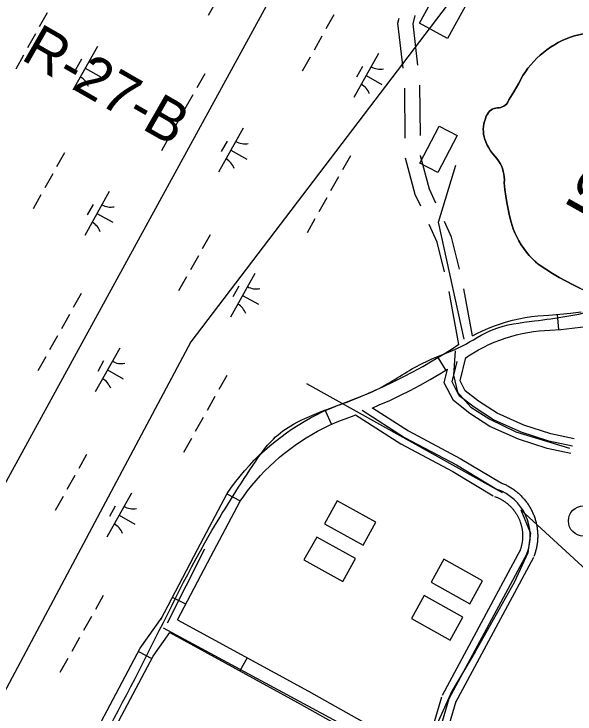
# Model space of a CAD drawing. Extents: x 3913936 to 3933962, y 195330 to 217741.
# Drawn here: x 3928535 to 3929093, y 208398 to 209094 of the extents above; entities that cross this region are included whole.
import ezdxf

# ---------------------------------------------------------------- set-up
doc = ezdxf.new("R2010")
doc.units = 0
for name, color, linetype in [('V-BLDG-OTLN', 7, 'Continuous'), ('V-RIVR-IDEN', 7, 'Continuous'), ('V-RIVR-RANG-IDEN', 7, 'Continuous'), ('V-ROAD-CNTR', 7, 'Continuous'), ('V-TOPO-SHOR', 7, 'Continuous'), ('V-TOPO-TOWR', 7, 'Continuous'), ('V-UTIL-LINE', 7, 'Continuous'), ('V-WETL-SWMP', 7, 'Continuous')]:
    doc.layers.add(name, color=color, linetype=linetype)

msp = doc.modelspace()

# ---------------------------------------------------------------- linework, layer by layer
at = {"layer": 'V-BLDG-OTLN'}
for points in [[(3928938.51, 209085.2), (3928961.65, 209127.6), (3928989.66, 209112.32), (3928966.52, 209069.91)], [(3928938.98, 208945.79), (3928958.17, 208982.69), (3928975.95, 208973.44), (3928956.76, 208936.54)], [(3928895.17, 208588.41), (3928856.57, 208609.83), (3928843.88, 208586.96), (3928882.47, 208565.54)], [(3928874.79, 208552.28), (3928836.2, 208573.7), (3928823.5, 208550.83), (3928862.1, 208529.4)], [(3929001.34, 208530.17), (3928962.74, 208551.59), (3928950.05, 208528.71), (3928988.64, 208507.29)], [(3928981.71, 208493.91), (3928943.12, 208515.33), (3928930.42, 208492.46), (3928969.02, 208471.04)]]:
    msp.add_lwpolyline(points, close=True, dxfattribs=at)
at = {"layer": 'V-ROAD-CNTR'}
for p, q in [((3928924.39, 208970.57), (3928923.87, 209020.56)), ((3928939.36, 208973.33), (3928938.84, 209023.32)), ((3928977.74, 208765.41), (3928968.01, 208818.05)), ((3928991.42, 208773.91), (3928982.76, 208820.78)), ((3929075.64, 208795.14), (3929076.77, 208780.18)), ((3928956.82, 208752.31), (3928964.58, 208739.48)), ((3928844.76, 208699.53), (3928850.89, 208685.84)), ((3928746.88, 208616.62), (3928760.12, 208609.58)), ((3928692.2, 208513.99), (3928705.59, 208507.24)), ((3928658.87, 208459.89), (3928672.12, 208452.87)), ((3928766.83, 208453.57), (3928759.64, 208440.41))]:
    msp.add_line(p, q, dxfattribs=at)
for points in [[(3928922.25, 209040.47), (3928917.11, 209085.13), (3928918.16, 209090.07)], [(3928937.03, 209043.22), (3928932.29, 209084.41), (3928934.06, 209092.76)], [(3928939.72, 208903.03), (3928934.34, 208914.7), (3928924.73, 208950.59)], [(3928954.91, 208905.91), (3928948.5, 208919.82), (3928939.57, 208953.18), (3928939.57, 208953.33)], [(3928983.1, 208770.49), (3928957.57, 208887.13), (3928974.71, 208943.85)], [(3928978.21, 208840.25), (3928970.48, 208872.11), (3928963.28, 208887.74)], [(3928963.44, 208837.52), (3928956.25, 208867.16), (3928948.09, 208884.87)], [(3928991.18, 208773.77), (3928995.66, 208776.14), (3929001.37, 208778.89), (3929007.18, 208781.44), (3929013.07, 208783.78), (3929019.05, 208785.89), (3929025.11, 208787.79), (3929031.22, 208789.46), (3929037.39, 208790.91), (3929043.61, 208792.14), (3929049.88, 208793.13), (3929056.29, 208793.91), (3929067.36, 208794.51), (3929078.08, 208795.33), (3929088.78, 208796.38), (3929099.46, 208797.66)], [(3928984.49, 208752.16), (3928987.35, 208754.05), (3928992.29, 208757.15), (3928997.31, 208760.04), (3929002.43, 208762.75), (3929007.65, 208765.27), (3929012.95, 208767.6), (3929018.34, 208769.73), (3929023.8, 208771.66), (3929029.33, 208773.39), (3929034.92, 208774.92), (3929040.56, 208776.25), (3929046.24, 208777.37), (3929051.96, 208778.28), (3929057.6, 208778.96), (3929068.33, 208779.54), (3929079.38, 208780.38), (3929090.41, 208781.46), (3929101.41, 208782.79)], [(3928717.56, 208561.42), (3928747.16, 208617.15), (3928751.38, 208623.2), (3928755.57, 208628.84), (3928759.93, 208634.35), (3928764.46, 208639.72), (3928769.15, 208644.96), (3928773.98, 208650.05), (3928778.97, 208655), (3928784.11, 208659.79), (3928789.39, 208664.44), (3928794.81, 208668.91), (3928800.35, 208673.23), (3928806.03, 208677.37), (3928811.83, 208681.34), (3928817.74, 208685.14), (3928823.76, 208688.76), (3928829.89, 208692.19), (3928836.12, 208695.44), (3928842.45, 208698.5), (3928848.86, 208701.37), (3928855.36, 208704.04), (3928861.83, 208706.48), (3928865.36, 208707.82), (3928872.17, 208710.4), (3928882.38, 208714.51), (3928892.5, 208718.83), (3928902.53, 208723.34), (3928912.47, 208728.06), (3928922.31, 208732.98), (3928932.05, 208738.1), (3928941.68, 208743.41), (3928951.2, 208748.91), (3928960.62, 208754.61), (3928969.91, 208760.49), (3928977.73, 208765.67)], [(3928973.98, 208759.07), (3928972.29, 208734.65), (3928976.41, 208717.78), (3928989.5, 208702.87), (3929008.65, 208691.07), (3929034.39, 208678.42), (3929087.88, 208662.16)], [(3929090.84, 208664.14), (3929067.42, 208669.11), (3929039.72, 208678.13), (3929012.18, 208690.33), (3928992.96, 208702.78), (3928978.17, 208714.36), (3928971.17, 208728.13), (3928975.99, 208748.36)], [(3929092.4, 208671.47), (3929069.37, 208676.36), (3929042.41, 208685.14), (3929015.76, 208696.95), (3928997.32, 208708.89), (3928984.1, 208719.24), (3928979.1, 208729.08), (3928984.66, 208752.42)], [(3928891.25, 208701.99), (3928898.52, 208705.09), (3928908.83, 208709.73), (3928919.04, 208714.58), (3928929.15, 208719.63), (3928939.16, 208724.89), (3928949.06, 208730.35), (3928958.84, 208736), (3928966.56, 208740.68)], [(3929089.28, 208656.8), (3929065.48, 208661.85), (3929037.04, 208671.11), (3929008.6, 208683.72), (3928988.6, 208696.66), (3928972.24, 208709.48), (3928963.23, 208727.19), (3928966.47, 208740.78)], [(3929021.06, 208617.58), (3928826.4, 208726.25)], [(3928881.55, 208699.87), (3928923.72, 208672.88), (3928975.47, 208645.43), (3929015.85, 208621.09)], [(3928891.79, 208702.22), (3928927.51, 208679.36), (3928979.16, 208651.96), (3929019.73, 208627.51)], [(3928730.81, 208554.39), (3928759.98, 208609.31), (3928763.55, 208614.42), (3928767.47, 208619.7), (3928771.56, 208624.86), (3928775.79, 208629.89), (3928780.17, 208634.79), (3928784.7, 208639.56), (3928789.38, 208644.19), (3928794.18, 208648.68), (3928799.12, 208653.02), (3928804.19, 208657.21), (3928809.38, 208661.25), (3928814.69, 208665.12), (3928820.12, 208668.84), (3928825.65, 208672.39), (3928831.29, 208675.78), (3928837.03, 208679), (3928842.86, 208682.04), (3928848.78, 208684.9), (3928854.78, 208687.59), (3928860.86, 208690.09), (3928867.13, 208692.45), (3928870.68, 208693.8), (3928875.03, 208695.45)], [(3928874.72, 208695.33), (3928919.94, 208666.4), (3928971.77, 208638.9), (3929011.98, 208614.67)], [(3929018.38, 208628.15), (3929019.27, 208627.83), (3929020.21, 208627.47), (3929021.1, 208627.11), (3929022.01, 208626.73), (3929022.94, 208626.32), (3929023.81, 208625.91), (3929024.7, 208625.49), (3929025.6, 208625.03), (3929026.47, 208624.57), (3929027.34, 208624.09), (3929028.17, 208623.61), (3929029.02, 208623.11), (3929029.89, 208622.57), (3929030.71, 208622.03), (3929031.52, 208621.49), (3929032.33, 208620.93), (3929033.14, 208620.34), (3929033.93, 208619.75), (3929034.72, 208619.14), (3929035.47, 208618.53), (3929036.23, 208617.89), (3929036.99, 208617.24), (3929037.71, 208616.59), (3929038.44, 208615.92), (3929039.16, 208615.23), (3929039.86, 208614.53), (3929040.54, 208613.83), (3929041.22, 208613.1), (3929041.89, 208612.35), (3929042.53, 208611.63), (3929043.16, 208610.88), (3929043.79, 208610.1), (3929044.41, 208609.31), (3929044.99, 208608.54), (3929045.58, 208607.74), (3929046.16, 208606.91), (3929046.7, 208606.11), (3929047.24, 208605.3), (3929047.78, 208604.44), (3929048.28, 208603.6), (3929048.78, 208602.74), (3929049.25, 208601.89), (3929049.72, 208601.02), (3929050.18, 208600.12), (3929050.61, 208599.25), (3929051.02, 208598.36), (3929051.44, 208597.44), (3929051.82, 208596.54), (3929052.19, 208595.64), (3929052.55, 208594.71), (3929052.89, 208593.78), (3929053.22, 208592.83), (3929053.52, 208591.9), (3929053.81, 208590.98), (3929054.09, 208590.01), (3929054.35, 208589.05), (3929054.58, 208588.11), (3929054.81, 208587.13), (3929055.02, 208586.15), (3929055.21, 208585.2), (3929055.38, 208584.24), (3929055.54, 208583.26), (3929055.68, 208582.26), (3929055.8, 208581.29), (3929055.91, 208580.32), (3929056, 208579.32), (3929056.07, 208578.33), (3929056.12, 208577.36), (3929056.16, 208576.36), (3929056.18, 208575.37), (3929056.18, 208574.4), (3929056.17, 208573.4), (3929056.13, 208572.42), (3929056.09, 208571.42), (3929056.02, 208570.43), (3929055.94, 208569.47), (3929055.84, 208568.49), (3929055.71, 208567.47), (3929055.58, 208566.5), (3929055.43, 208565.55), (3929055.26, 208564.57), (3929055.08, 208563.61), (3929054.87, 208562.61), (3929054.64, 208561.65), (3929054.42, 208560.72), (3929054.16, 208559.74), (3929053.88, 208558.79), (3929053.61, 208557.87), (3929053.3, 208556.91), (3929052.98, 208555.98), (3929052.65, 208555.05), (3929052.36, 208554.31)], [(3929013.32, 208614.03), (3929014.05, 208613.77), (3929014.71, 208613.52), (3929015.41, 208613.24), (3929016.08, 208612.95), (3929016.73, 208612.67), (3929017.4, 208612.35), (3929018.06, 208612.04), (3929018.69, 208611.72), (3929019.33, 208611.38), (3929019.97, 208611.02), (3929020.61, 208610.65), (3929021.24, 208610.28), (3929021.84, 208609.91), (3929022.44, 208609.52), (3929023.06, 208609.1), (3929023.65, 208608.69), (3929024.24, 208608.26), (3929024.82, 208607.83), (3929025.39, 208607.39), (3929025.97, 208606.92), (3929026.52, 208606.46), (3929027.06, 208606), (3929027.61, 208605.5), (3929028.14, 208605.01), (3929028.66, 208604.51), (3929029.18, 208603.99), (3929029.69, 208603.46), (3929030.18, 208602.94), (3929030.66, 208602.41), (3929031.15, 208601.85), (3929031.62, 208601.29), (3929032.07, 208600.74), (3929032.51, 208600.18), (3929032.97, 208599.58), (3929033.39, 208599), (3929033.8, 208598.42), (3929034.22, 208597.8), (3929034.62, 208597.18), (3929034.99, 208596.59), (3929035.37, 208595.96), (3929035.74, 208595.33), (3929036.09, 208594.69), (3929036.44, 208594.05), (3929036.76, 208593.42), (3929037.09, 208592.75), (3929037.4, 208592.09), (3929037.69, 208591.45), (3929037.97, 208590.77), (3929038.25, 208590.09), (3929038.51, 208589.42), (3929038.77, 208588.73), (3929039, 208588.06), (3929039.22, 208587.36), (3929039.45, 208586.65), (3929039.64, 208585.97), (3929039.83, 208585.28), (3929040.01, 208584.55), (3929040.18, 208583.85), (3929040.32, 208583.16), (3929040.47, 208582.44), (3929040.6, 208581.7), (3929040.71, 208581), (3929040.81, 208580.29), (3929040.9, 208579.56), (3929040.98, 208578.83), (3929041.05, 208578.11), (3929041.1, 208577.39), (3929041.14, 208576.65), (3929041.17, 208575.94), (3929041.18, 208575.22), (3929041.18, 208574.48), (3929041.17, 208573.75), (3929041.15, 208573.04), (3929041.11, 208572.32), (3929041.06, 208571.59), (3929041, 208570.84), (3929040.93, 208570.13), (3929040.84, 208569.43), (3929040.74, 208568.71), (3929040.63, 208567.97), (3929040.5, 208567.25), (3929040.37, 208566.54), (3929040.22, 208565.85), (3929040.06, 208565.14), (3929039.88, 208564.41), (3929039.7, 208563.73), (3929039.5, 208563.03), (3929039.28, 208562.32), (3929039.07, 208561.64), (3929038.83, 208560.95), (3929038.58, 208560.26), (3929038.35, 208559.68)], [(3930823.01, 206963.04), (3929039.41, 208600.73), (3929049.15, 208577.59), (3929046.49, 208558.09), (3929032.64, 208528.59), (3928993.92, 208459.57), (3928970.67, 208420.27), (3928954.36, 208384.07), (3928945.59, 208353.96), (3928950.18, 208316.41), (3928961.96, 208239.89), (3928974.02, 208141.9), (3928981.7, 208066.95), (3928978.5, 208011.84), (3928972.63, 207973.03), (3928962.24, 207947.24), (3928936.56, 207903.58), (3928904.2, 207841.96)], [(3928680.95, 208491.66), (3928717.56, 208561.42)], [(3928687.65, 208488.29), (3928724.81, 208562.06)], [(3929038.75, 208560.54), (3928961.18, 208416.11)], [(3928697.61, 208491.39), (3928730.81, 208554.39)], [(3929045.36, 208556.99), (3928967.79, 208412.57)], [(3929051.96, 208553.44), (3928974.39, 208409.02)], [(3928044.19, 207343.61), (3928094.47, 207444.55), (3928133.32, 207517.5), (3928180.5, 207605.25), (3928235.42, 207695.27), (3928288.75, 207774.86), (3928328.21, 207845.05), (3928371.81, 207914.97), (3928403.35, 207978.71), (3928448.6, 208063.04), (3928487.61, 208140.09), (3928551.26, 208257.15), (3928589.13, 208328.33), (3928660.52, 208463.01), (3928682.44, 208493.91)], [(3928697.61, 208491.39), (3928827.89, 208420.21), (3928926.42, 208364.82), (3928942.48, 208352.95)], [(3928947.64, 208339.98), (3928899.56, 208366.53), (3928683.7, 208482.82)], [(3928500.9, 208133.12), (3928564.47, 208250.04), (3928602.37, 208321.29), (3928673.32, 208455.12), (3928689.91, 208478.51), (3928820.62, 208407.09), (3928918.26, 208352.2), (3928940.13, 208336.04), (3928946.44, 208313.53), (3928967.35, 208141.02), (3928975.79, 208057.33), (3928972.53, 208007.03)], [(3928942.48, 208352.95), (3928960.59, 208414.68)], [(3928967.79, 208412.57), (3928948.91, 208348.2)], [(3928954.46, 208340.49), (3928974.98, 208410.45)]]:
    msp.add_lwpolyline(points, dxfattribs=at)
msp.add_arc((3928999.57, 208574.75), 49.12, 338.79873, 70.63267, dxfattribs=at)
msp.add_spline([(3928525.94, 208199.58), (3928663.47, 208448.7), (3928729.28, 208575.65), (3928772.51, 208644.8), (3928793.04, 208671.23), (3928813.16, 208685.99), (3928849.99, 208702.06), (3928901.39, 208723.29), (3928941.15, 208746.48), (3928980.61, 208763.64), (3929011.73, 208780.24), (3929053.09, 208788.77), (3929116.61, 208799.68), (3929152.59, 208808.41), (3929198.09, 208822), (3929228.27, 208840.26), (3929280.48, 208872.74), (3929342.15, 208906.58), (3929394.32, 208930.8), (3929439.03, 208947.65), (3929467.84, 208956.79), (3929496.68, 208976.36), (3929523.63, 209009.71), (3929552.13, 209061.34), (3929562.8, 209097.59), (3929549.93, 209122.48), (3929531.62, 209153.63), (3929490.5, 209225.48), (3929461.64, 209289.09), (3929459.62, 209329.37)], degree=3, dxfattribs=at)
at = {"layer": 'V-TOPO-SHOR'}
msp.add_lwpolyline([(3929098.67, 208821.18), (3929091.57, 208824.61), (3929084.56, 208828.23), (3929077.65, 208832.03), (3929070.85, 208836.02), (3929064.15, 208840.19), (3929057.57, 208844.54), (3929054.17, 208847.45), (3929050.92, 208850.55), (3929047.85, 208853.81), (3929044.96, 208857.24), (3929042.27, 208860.81), (3929039.76, 208864.53), (3929037.46, 208868.38), (3929035.38, 208872.34), (3929033.51, 208876.41), (3929031.86, 208880.58), (3929029.91, 208886.97), (3929028.18, 208893.42), (3929026.67, 208899.92), (3929025.39, 208906.47), (3929024.34, 208913.07), (3929023.51, 208919.69), (3929022.91, 208926.35), (3929023.01, 208929.18), (3929022.87, 208932.02), (3929022.5, 208934.84), (3929021.91, 208937.61), (3929021.08, 208940.33), (3929020.04, 208942.98), (3929018.79, 208945.52), (3929017.33, 208947.96), (3929015.67, 208950.27), (3929013.38, 208952.72), (3929011.26, 208955.31), (3929009.31, 208958.04), (3929007.55, 208960.89), (3929005.97, 208963.85), (3929004.6, 208966.9), (3929003.64, 208969.34), (3929002.9, 208971.86), (3929002.39, 208974.43), (3929002.11, 208977.04), (3929002.06, 208979.66), (3929002.26, 208982.27), (3929002.68, 208984.86), (3929003.34, 208987.4), (3929004.22, 208989.87), (3929004.64, 208991.55), (3929005.28, 208993.17), (3929006.11, 208994.7), (3929007.14, 208996.1), (3929008.33, 208997.37), (3929009.68, 208998.47), (3929011.15, 208999.39), (3929012.73, 209000.12), (3929014.39, 209000.64), (3929016.1, 209000.94), (3929017.76, 209000.99), (3929019.4, 209001.28), (3929020.98, 209001.8), (3929022.46, 209002.54), (3929023.83, 209003.48), (3929025.05, 209004.61), (3929026.1, 209005.89), (3929026.95, 209007.32), (3929027.59, 209008.85), (3929032.49, 209016.74), (3929037.12, 209024.79), (3929041.46, 209032.99), (3929043.9, 209036.68), (3929046.52, 209040.24), (3929049.3, 209043.68), (3929052.23, 209046.98), (3929055.33, 209050.14), (3929058.56, 209053.15), (3929061.94, 209056.01), (3929065.44, 209058.7), (3929069.07, 209061.22), (3929072.81, 209063.57), (3929076.66, 209065.74), (3929080.61, 209067.73), (3929084.65, 209069.53), (3929088.77, 209071.14), (3929092.95, 209072.55), (3929109.07, 209076.16)], dxfattribs=at)
at = {"layer": 'V-TOPO-TOWR'}
msp.add_circle((3929101.74, 208589.67), 15, dxfattribs=at)
at = {"layer": 'V-UTIL-LINE'}
for points in [[(3928017.72, 207698.29), (3929347.59, 210128.96), (3930421.75, 211210.28)], [(3930525.66, 211151.39), (3928710.93, 208768), (3928100.1, 207621.2)]]:
    msp.add_lwpolyline(points, dxfattribs=at)
at = {"layer": 'V-WETL-SWMP'}
for p, q in [((3928752.69, 209136.28), (3928728.19, 209092.7)), ((3928567.92, 209095.26), (3928560.08, 209081.32)), ((3928853.11, 209093.26), (3928845.27, 209079.31)), ((3928556.16, 209074.34), (3928548.32, 209060.4)), ((3928841.35, 209072.34), (3928833.51, 209058.39)), ((3928618.09, 209061.99), (3928593.59, 209018.41)), ((3928897.69, 209054.77), (3928873.19, 209011.19)), ((3928544.4, 209053.42), (3928536.56, 209039.48)), ((3928602.05, 209049.21), (3928596.17, 209038.75)), ((3928829.59, 209051.41), (3928821.75, 209037.47)), ((3928605.84, 209040.2), (3928621.53, 209031.38)), ((3928881.65, 209041.99), (3928875.77, 209031.53)), ((3928724.68, 209034.68), (3928716.84, 209020.73)), ((3928885.44, 209032.98), (3928901.13, 209024.16)), ((3928712.92, 209013.76), (3928705.08, 208999.81)), ((3928701.16, 208992.83), (3928693.32, 208978.89)), ((3928763.09, 208980.48), (3928738.59, 208936.9)), ((3928689.4, 208971.91), (3928681.56, 208957.97)), ((3928747.05, 208967.7), (3928741.17, 208957.24)), ((3928750.84, 208958.69), (3928766.53, 208949.87)), ((3928585.14, 208956.01), (3928577.3, 208942.06)), ((3928869.68, 208953.17), (3928861.84, 208939.22)), ((3928573.38, 208935.09), (3928565.54, 208921.14)), ((3928857.92, 208932.25), (3928850.08, 208918.3)), ((3928629.72, 208917.52), (3928605.22, 208873.94)), ((3928561.62, 208914.16), (3928553.78, 208900.22)), ((3928846.16, 208911.33), (3928838.32, 208897.38)), ((3928613.68, 208904.74), (3928607.8, 208894.28)), ((3928617.47, 208895.73), (3928633.16, 208886.91)), ((3928834.4, 208890.4), (3928826.56, 208876.46)), ((3928730.14, 208874.5), (3928722.3, 208860.55)), ((3928718.38, 208853.58), (3928710.54, 208839.63)), ((3928706.62, 208832.66), (3928698.78, 208818.71)), ((3928774.72, 208836.01), (3928750.22, 208792.43)), ((3928758.68, 208823.23), (3928752.8, 208812.77)), ((3928601.71, 208815.92), (3928593.87, 208801.97)), ((3928762.47, 208814.22), (3928778.16, 208805.4)), ((3928589.95, 208795), (3928582.11, 208781.05)), ((3928578.19, 208774.08), (3928570.35, 208760.13)), ((3928640.11, 208761.72), (3928615.61, 208718.14)), ((3928566.43, 208753.15), (3928558.59, 208739.21)), ((3928624.08, 208748.94), (3928618.2, 208738.48)), ((3928627.86, 208739.93), (3928643.55, 208731.11)), ((3928746.71, 208734.41), (3928738.87, 208720.46)), ((3928734.95, 208713.49), (3928727.11, 208699.54)), ((3928723.18, 208692.57), (3928715.34, 208678.62)), ((3928711.42, 208671.65), (3928703.58, 208657.7)), ((3928607.17, 208655.74), (3928599.33, 208641.79)), ((3928595.41, 208634.82), (3928587.57, 208620.87)), ((3928651.74, 208617.25), (3928627.24, 208573.67)), ((3928583.65, 208613.9), (3928575.81, 208599.95)), ((3928635.71, 208604.47), (3928629.83, 208594.01)), ((3928639.49, 208595.46), (3928655.18, 208586.64)), ((3928623.73, 208515.65), (3928615.89, 208501.7)), ((3928611.97, 208494.73), (3928604.13, 208480.78)), ((3928600.21, 208473.81), (3928592.37, 208459.86)), ((3928588.45, 208452.89), (3928580.61, 208438.94))]:
    msp.add_line(p, q, dxfattribs=at)
for points in [[(3929109.07, 209076.16), (3929092.95, 209072.55), (3929088.77, 209071.14), (3929084.65, 209069.53), (3929080.61, 209067.73), (3929076.66, 209065.74), (3929072.81, 209063.57), (3929069.07, 209061.22), (3929065.44, 209058.7), (3929061.94, 209056.01), (3929058.56, 209053.15), (3929055.33, 209050.14), (3929052.23, 209046.98), (3929049.3, 209043.68), (3929046.52, 209040.24), (3929043.9, 209036.68), (3929041.46, 209032.99), (3929037.12, 209024.79), (3929032.49, 209016.74), (3929027.59, 209008.85), (3929026.95, 209007.32), (3929026.1, 209005.9), (3929025.05, 209004.61), (3929023.83, 209003.48), (3929022.46, 209002.54), (3929020.98, 209001.8), (3929019.4, 209001.28), (3929017.76, 209000.99), (3929016.1, 209000.94), (3929014.39, 209000.64), (3929012.73, 209000.12), (3929011.15, 208999.39), (3929009.68, 208998.47), (3929008.33, 208997.37), (3929007.14, 208996.1), (3929006.11, 208994.7), (3929005.28, 208993.17), (3929004.64, 208991.55), (3929004.22, 208989.87), (3929003.34, 208987.4), (3929002.68, 208984.86), (3929002.25, 208982.27), (3929002.06, 208979.66), (3929002.11, 208977.04), (3929002.39, 208974.43), (3929002.9, 208971.86), (3929003.64, 208969.34), (3929004.6, 208966.9), (3929005.97, 208963.85), (3929007.54, 208960.89), (3929009.31, 208958.04), (3929011.26, 208955.31), (3929013.38, 208952.72), (3929015.67, 208950.27), (3929017.33, 208947.96), (3929018.79, 208945.52), (3929020.04, 208942.98), (3929021.08, 208940.33), (3929021.91, 208937.61), (3929022.5, 208934.84), (3929022.87, 208932.02), (3929023.01, 208929.18), (3929022.91, 208926.35), (3929023.51, 208919.7), (3929024.34, 208913.07), (3929025.39, 208906.48), (3929026.68, 208899.92), (3929028.18, 208893.42), (3929029.91, 208886.97), (3929031.86, 208880.58), (3929033.51, 208876.41), (3929035.38, 208872.34), (3929037.46, 208868.38), (3929039.76, 208864.53), (3929042.27, 208860.81), (3929044.96, 208857.24)], [(3929044.96, 208857.24), (3929047.85, 208853.81), (3929050.92, 208850.55), (3929054.16, 208847.45), (3929057.57, 208844.54), (3929064.15, 208840.19), (3929070.85, 208836.02), (3929077.65, 208832.03), (3929084.56, 208828.23), (3929091.57, 208824.61), (3929098.67, 208821.18), (3929105.86, 208817.93), (3929113.14, 208814.89), (3929120.49, 208812.03), (3929131.97, 208806.88)]]:
    msp.add_lwpolyline(points, dxfattribs=at)
for centre, start, end in [((3928619.58, 209064.16), 239.88608, 281.42974), ((3928899.18, 209056.94), 239.88608, 281.42974), ((3928592.51, 209016), 19.88608, 61.42973), ((3928872.11, 209008.78), 19.88608, 61.42973), ((3928764.58, 208982.65), 239.88608, 281.42974), ((3928737.51, 208934.49), 19.88608, 61.42973), ((3928631.21, 208919.69), 239.88608, 281.42974), ((3928604.14, 208871.54), 19.88608, 61.42973), ((3928776.21, 208838.18), 239.88608, 281.42974), ((3928749.14, 208790.03), 19.88608, 61.42973), ((3928641.61, 208763.89), 239.88608, 281.42974), ((3928614.54, 208715.74), 19.88608, 61.42973), ((3928653.24, 208619.42), 239.88608, 281.42974), ((3928626.17, 208571.27), 19.88608, 61.42973)]:
    msp.add_arc(centre, 17.62, start, end, dxfattribs=at)

# ---------------------------------------------------------------- texts
at = {"layer": 'V-RIVR-IDEN'}
msp.add_text('Water', height=50, rotation=240.67305, dxfattribs=at).set_placement((3929166.08, 209050.47))
at = {"layer": 'V-RIVR-RANG-IDEN'}
msp.add_text('R-27-B', height=41.5, rotation=330.16058, dxfattribs=at).set_placement((3928540.67, 209049.61))

doc.saveas('drawing.dxf')
